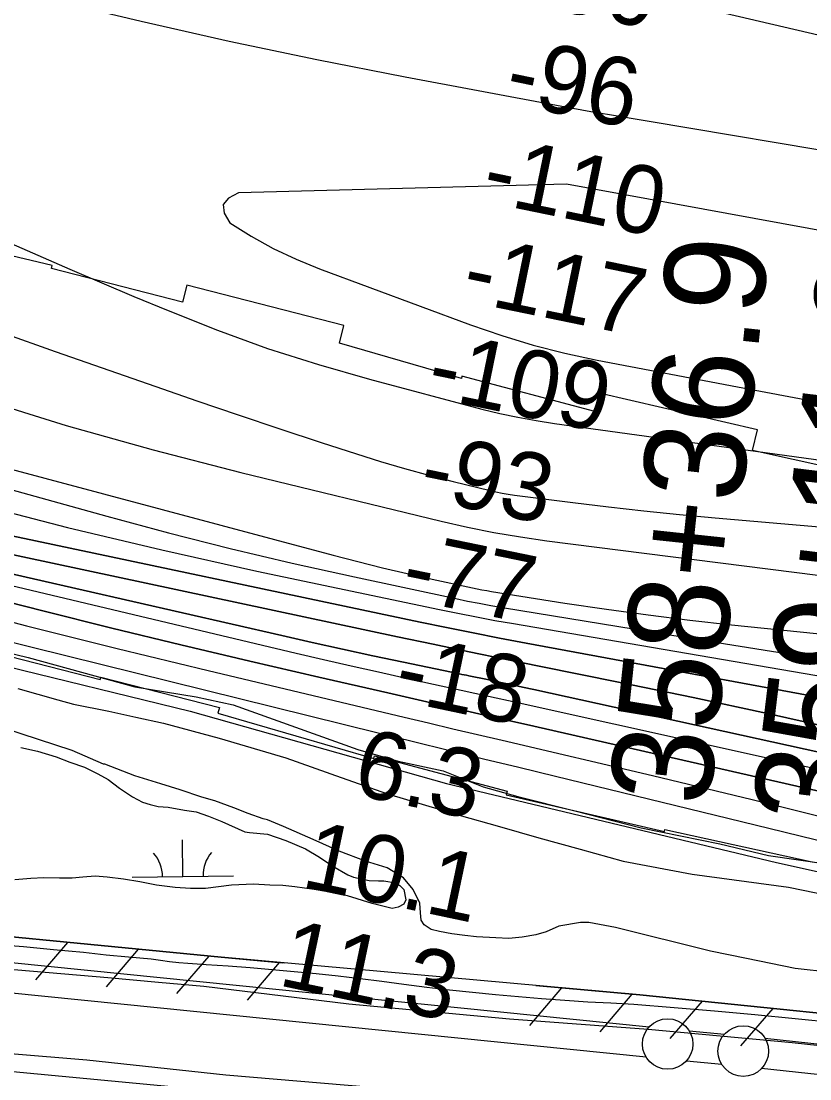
# Model space of a CAD drawing. Extents: x 3704301 to 3742427, y 506229 to 532009.
# Drawn here: x 3712174 to 3712953, y 519013 to 520058 of the extents above; entities that cross this region are included whole.
import ezdxf

# ---------------------------------------------------------------- set-up
doc = ezdxf.new("R2010")
doc.units = 0
for name, color, linetype in [('V-FLOD-BASE', 7, 'Continuous'), ('V-LEVE-TOET', 7, 'Continuous'), ('V-RIVR-EDGE', 7, 'Continuous'), ('V-RIVR-RANG', 7, 'Continuous'), ('V-ROAD-CNTR', 7, 'Continuous'), ('V-RRAP-FSHR', 7, 'Continuous'), ('V-RRAP-RVMT', 7, 'Continuous'), ('V-SITE-VEGE', 7, 'Continuous'), ('V-SURV-IDEN', 7, 'Continuous'), ('V-SURV-LINE', 7, 'Continuous'), ('V-TOPO-DPTH', 7, 'Continuous'), ('V-TOPO-MAJR', 7, 'Continuous'), ('V-TOPO-MINR', 7, 'Continuous'), ('V-TOPO-WATR', 7, 'Continuous'), ('V-WETL-SWMP', 7, 'Continuous')]:
    doc.layers.add(name, color=color, linetype=linetype)

msp = doc.modelspace()

# ---------------------------------------------------------------- linework, layer by layer
at = {"layer": 'V-FLOD-BASE'}
for points in [[(3712309.3, 519108.6), (3712259.2, 519113.2), (3712123.5, 519124.7)], [(3713057.3, 519035.8), (3712935.8, 519048.8), (3712793.5, 519062.2), (3712656.3, 519072.2), (3712497.5, 519087), (3712354.2, 519104.6), (3712309.3, 519108.6)]]:
    msp.add_lwpolyline(points, dxfattribs=at)
at = {"layer": 'V-LEVE-TOET'}
for points in [[(3711586.2, 519172), (3711588.4, 519170.9), (3711722.8, 519116.9), (3711798, 519088.7), (3711821.7, 519081.2), (3711868.5, 519070.4), (3711901.1, 519063.9), (3711971.1, 519056.5), (3712087.4, 519044.5), (3712238.7, 519032.1), (3712375.8, 519017.3), (3712543.6, 519003), (3712718.4, 518986.2), (3712896.6, 518967.7), (3713058.8, 518953.9)], [(3712978.7, 519068.5), (3712938.9, 519072.5), (3712899, 519076.4), (3712859.1, 519080.1), (3712819.2, 519083.5), (3712779.3, 519086.8), (3712756.5, 519087.9), (3712733.7, 519089.1), (3712710.9, 519090.6), (3712688.1, 519092.3), (3712665.4, 519094.2), (3712642.6, 519096.3), (3712619.9, 519098.5), (3712597.2, 519101), (3712574.5, 519103.7), (3712551.9, 519106.6), (3712530.3, 519109.4), (3712508.6, 519112.1), (3712487, 519114.6), (3712465.3, 519117), (3712443.6, 519119.1), (3712421.9, 519121.1), (3712400.1, 519122.9), (3712378.4, 519124.5), (3712356.6, 519126), (3712347.5, 519126.5), (3712338.4, 519127.2), (3712329.4, 519128), (3712320.3, 519129), (3712311.3, 519130.2), (3712302.3, 519131.5), (3712279.9, 519133.4), (3712257.5, 519135.6), (3712235.1, 519138), (3712205.5, 519140.9), (3712175.8, 519143.6), (3712146.1, 519146.1)]]:
    msp.add_lwpolyline(points, dxfattribs=at)
at = {"layer": 'V-RIVR-EDGE'}
msp.add_lwpolyline([(3711522.5, 519662.9), (3711583.7, 519639.3), (3711661.7, 519603.7), (3711684.4, 519586.3), (3711714.3, 519538.2), (3711754.5, 519519.4), (3711864.3, 519485), (3711918.3, 519483.6), (3711999.3, 519464.8), (3712076.1, 519455), (3712180.5, 519429.5), (3712286.1, 519400.5), (3712346.7, 519390.7), (3712383.3, 519382.8), (3712506.3, 519338.7), (3712546.4, 519327.2), (3712590.8, 519317.5), (3712630.4, 519301.8), (3712664.6, 519292.1), (3712721, 519278.1), (3712786.4, 519261.2), (3712864.4, 519245.4), (3712912.4, 519233.8), (3713028.8, 519217.3)], dxfattribs=at)
at = {"layer": 'V-ROAD-CNTR'}
msp.add_lwpolyline([(3713157.6, 518919.9), (3712918.7, 518948.2), (3712531.1, 518985.5), (3712067.6, 519029.6), (3711906, 519048.2), (3711880.7, 519050.4), (3711857.5, 519053.6), (3711843.4, 519056.9), (3711828.4, 519062.3), (3711804.8, 519068.1), (3711783.6, 519074.2), (3711747.7, 519088.7), (3711454.3, 519226.5), (3711379.5, 519260.4), (3711253.9, 519313.1), (3711117.8, 519371.9), (3710938, 519451.5), (3710654.9, 519565.5), (3710319.9, 519704.9), (3710100.2, 519789)], dxfattribs=at)
at = {"layer": 'V-RRAP-FSHR'}
for p, q in [((3712219.6, 519148.1), (3712187.9, 519111)), ((3712289.3, 519141.3), (3712257.6, 519104.2)), ((3712359, 519134.6), (3712327.2, 519097.5)), ((3712428.7, 519128.2), (3712397.2, 519090.9)), ((3712707.6, 519103.3), (3712676.1, 519065.9)), ((3712777.3, 519097), (3712745.8, 519059.7)), ((3712846.9, 519090), (3712815, 519053.1)), ((3712916.6, 519082.9), (3712884.6, 519045.9))]:
    msp.add_line(p, q, dxfattribs=at)
for points in [[(3709741.8, 520362.4), (3710017.7, 520222), (3710534.8, 519997.8), (3710940.4, 519847.9), (3711083.4, 519806), (3711220.5, 519772.7), (3711363.5, 519722.1), (3711531.9, 519623.8), (3711655.2, 519570.7), (3711808.3, 519520), (3711956.1, 519471.1), (3712143.5, 519424.7), (3712340.7, 519376.7), (3712594.2, 519305.2), (3712920.3, 519227.2), (3713163.8, 519173.1), (3713383, 519116.6), (3713629.9, 519034.4)], [(3713107.9, 519063.3), (3712785.1, 519096.3), (3712371.4, 519133.4), (3712005, 519169), (3711979.2, 519171.5), (3711951.5, 519178.8), (3711919.2, 519185.7), (3711888.2, 519193.2), (3711846.9, 519208.1), (3711688.8, 519275.3), (3711690.4, 519291.5), (3711692, 519302.8), (3711691.2, 519314), (3711687.9, 519322), (3711683.4, 519329.2), (3711679.4, 519332.2), (3711670.9, 519339.4), (3711537.2, 519400.4)], [(3713107.9, 519063.3), (3712785.1, 519096.3), (3712371.4, 519133.4), (3712005, 519169), (3711979.2, 519171.5), (3711951.5, 519178.8), (3711919.2, 519185.7), (3711888.2, 519193.2), (3711846.9, 519208.1), (3711688.8, 519275.3), (3711690.4, 519291.5), (3711692, 519302.8), (3711691.2, 519314), (3711687.9, 519322), (3711683.4, 519329.2), (3711679.4, 519332.2), (3711670.9, 519339.4), (3711537.2, 519400.4)], [(3711693, 519273.5), (3711846.9, 519208.1), (3711888.2, 519193.2), (3711919.2, 519185.7), (3711951.5, 519178.8), (3711979.2, 519171.5), (3712005, 519169), (3712371.4, 519133.4), (3712431.7, 519128)], [(3711725.5, 519259.7), (3711846.9, 519208.1), (3711888.2, 519193.2), (3711919.2, 519185.7), (3711951.5, 519178.8), (3711979.2, 519171.5), (3712005, 519169), (3712371.4, 519133.4), (3712433.9, 519127.8)], [(3712682.4, 519105.5), (3712785.1, 519096.3), (3713107.9, 519063.3), (3713318.5, 519044.2), (3713343.3, 519041.8), (3713357.6, 519037.2), (3713370.3, 519031.9), (3713371.6, 519030.7)], [(3712686.6, 519105.1), (3712785.1, 519096.3), (3713107.9, 519063.3), (3713318.5, 519044.2), (3713343.3, 519041.8), (3713357.6, 519037.2), (3713357.9, 519037.1)]]:
    msp.add_lwpolyline(points, dxfattribs=at)
at = {"layer": 'V-RRAP-RVMT'}
for p, q in [((3712204.3, 519816.8), (3712080, 519846.6)), ((3712203.6, 519813.8), (3712204.3, 519816.8)), ((3712333.1, 519780.7), (3712203.6, 519813.8)), ((3712337.3, 519797.4), (3712333.1, 519780.7)), ((3712492.7, 519757.7), (3712337.3, 519797.4)), ((3712488.2, 519740.2), (3712492.7, 519757.7)), ((3712608.8, 519705.2), (3712488.2, 519740.2)), ((3712609.4, 519707.5), (3712608.8, 519705.2)), ((3712740.7, 519672.5), (3712609.4, 519707.5)), ((3712744.9, 519690.9), (3712740.7, 519672.5)), ((3712901.4, 519654.6), (3712744.9, 519690.9)), ((3712896.7, 519634.1), (3712901.4, 519654.6)), ((3713023.2, 519606.2), (3712896.7, 519634.1)), ((3712114.4, 519443), (3712251.8, 519407.9)), ((3712251.8, 519407.9), (3712252.4, 519410.1)), ((3712252.4, 519410.1), (3712369.6, 519380.1)), ((3712369.6, 519380.1), (3712367.9, 519374.6)), ((3712367.9, 519374.6), (3712522.1, 519329.7)), ((3712522.1, 519329.7), (3712522.9, 519332.4)), ((3712522.9, 519332.4), (3712653.9, 519297.5)), ((3712653.9, 519297.5), (3712653.1, 519294)), ((3712653.1, 519294), (3712809.6, 519257.8)), ((3712809.6, 519257.8), (3712810, 519259.6)), ((3712810, 519259.6), (3712955.4, 519227.6))]:
    msp.add_line(p, q, dxfattribs=at)
at = {"layer": 'V-SITE-VEGE'}
for points in [[(3712170.5, 519398.8), (3712209.8, 519387.6), (3712225.3, 519383.4), (3712260.4, 519376.4), (3712287.1, 519370.5), (3712314.5, 519364.6), (3712369.2, 519349.9), (3712435.3, 519330.4), (3712490.1, 519310.9), (3712535.9, 519295), (3712573.4, 519283.8), (3712606.7, 519273.8), (3712646.6, 519262.6), (3712685.2, 519251.3), (3712726.3, 519240.1), (3712768.6, 519228.4), (3712837, 519215.4), (3712932.1, 519202.6), (3713012.5, 519186.1)], [(3712726.5, 519167.6), (3712705.1, 519164), (3712692.6, 519158.6), (3712682.5, 519155.6), (3712668.8, 519153.2), (3712655.8, 519152), (3712642.7, 519152.5), (3712623.6, 519153.7), (3712612.3, 519154.8), (3712599.2, 519156.6), (3712587.3, 519158.9), (3712579, 519160.7), (3712571.9, 519165.4), (3712568.9, 519170.2), (3712568.3, 519177.3), (3712567.7, 519186.8), (3712561.1, 519200.5), (3712551.5, 519211.8), (3712535.5, 519221.8), (3712514, 519228.3), (3712487.9, 519238.4), (3712462.3, 519249.6), (3712433.1, 519262.6), (3712417, 519269.1), (3712412.8, 519270.3), (3712398, 519275.6), (3712383.7, 519281), (3712365.2, 519288), (3712352.1, 519291.6), (3712330.7, 519298.7), (3712311.7, 519304.6), (3712286.1, 519312.8), (3712256.3, 519324.1), (3712255.1, 519324.1), (3712224.2, 519337.7), (3712157.5, 519359.5)], [(3712974.6, 519118.2), (3712938.9, 519122.3), (3712890.7, 519132.3), (3712855, 519139.4), (3712761, 519162.9), (3712734.8, 519167.6), (3712726.5, 519167.6)]]:
    msp.add_lwpolyline(points, dxfattribs=at)
at = {"layer": 'V-SURV-LINE'}
for points in [[(3711902.6, 519154.5), (3712794.3, 519064.7)], [(3712791.3, 519034.8), (3711899.6, 519124.6)], [(3712834, 519060.8), (3712868.9, 519057.5)], [(3712908.9, 519053.4), (3713308.9, 519010)], [(3712866.1, 519027.6), (3712831.2, 519030.9)], [(3713305.6, 518980.2), (3712905.6, 519023.6)]]:
    msp.add_lwpolyline(points, dxfattribs=at)
for centre in [(3712812.7, 519047.7), (3712887.4, 519040.7)]:
    msp.add_circle(centre, 25, dxfattribs=at)
at = {"layer": 'V-TOPO-DPTH'}
for points in [[(3712985, 519357.8), (3712911.5, 519374.3), (3712837.8, 519390.1), (3712764.1, 519405.3), (3712687.3, 519420.7), (3712651.8, 519427.9), (3712616.4, 519435.2), (3712580.9, 519442.6), (3712545.5, 519450.1), (3711863.2, 519595.7), (3711858.3, 519596.8), (3711853.4, 519598), (3711848.6, 519599.3), (3711843.8, 519600.7), (3711839, 519602.3), (3711834.2, 519603.9), (3711829.5, 519605.7), (3711824.9, 519607.6), (3711402.4, 519787.5)], [(3711402.4, 519787.5), (3711824.9, 519607.6), (3711829.5, 519605.7), (3711834.2, 519603.9), (3711839, 519602.3), (3711843.8, 519600.7), (3711848.6, 519599.3), (3711853.4, 519598), (3711858.3, 519596.8), (3711863.2, 519595.7), (3712545.5, 519450.1), (3712580.9, 519442.6), (3712616.4, 519435.2), (3712651.8, 519427.9), (3712687.3, 519420.7), (3712764.1, 519405.3), (3712837.8, 519390.1), (3712911.5, 519374.3), (3712985, 519357.8)], [(3713061.3, 519371.9), (3712672.7, 519443.8), (3712646.5, 519448.8), (3712620.3, 519453.9), (3712594.1, 519459.2), (3712567.9, 519464.6), (3712147.1, 519553.5), (3712095.8, 519565), (3712044.7, 519577.3), (3711993.9, 519590.8), (3711943.3, 519605.2), (3711903.6, 519616.9), (3711873.1, 519626.5), (3711842.9, 519636.5), (3711812.9, 519647.5), (3711783.1, 519658.9), (3711606.5, 519729.9), (3711516.4, 519766.1)], [(3713061.3, 519371.9), (3712672.7, 519443.8), (3712646.5, 519448.8), (3712620.3, 519453.9), (3712594.1, 519459.2), (3712567.9, 519464.6), (3712147.1, 519553.5), (3712095.8, 519565), (3712044.7, 519577.3), (3711993.9, 519590.8), (3711943.3, 519605.2), (3711903.6, 519616.9), (3711873.1, 519626.5), (3711842.9, 519636.5), (3711812.9, 519647.5), (3711783.1, 519658.9), (3711606.5, 519729.9), (3711516.4, 519766.1)], [(3711417, 519686.3), (3711759.7, 519561.6), (3711788.8, 519551.4), (3711817.9, 519541.5), (3711847.3, 519532.2), (3711876.8, 519523.3), (3711927.8, 519508.3), (3711983.1, 519492.5), (3712038.4, 519477.2), (3712093.9, 519462.6), (3712149.6, 519448.5), (3712526.7, 519355.1), (3712561.4, 519346.6), (3712596.1, 519338), (3712630.8, 519329.5), (3712665.6, 519321.1), (3712701.7, 519312.3), (3712754.5, 519299.5), (3712807.2, 519286.7), (3712860, 519273.8), (3712912.8, 519260.9), (3713498.6, 519117.6)], [(3711496.7, 519686.3), (3711578.2, 519655.6), (3711660.3, 519626.2), (3711795.5, 519579.9), (3711810.4, 519575), (3711825.4, 519570.3), (3711840.6, 519566), (3711855.8, 519562), (3712195.2, 519475.7), (3712263.3, 519458.7), (3712331.4, 519442), (3712399.6, 519425.9), (3712467.9, 519410.1), (3712536, 519394.6), (3712570.3, 519386.8), (3712604.7, 519379), (3712639, 519371.1), (3712673.3, 519363.3), (3713027.2, 519282.6)], [(3713027.2, 519282.6), (3712673.3, 519363.3), (3712639, 519371.1), (3712604.7, 519379), (3712570.3, 519386.8), (3712536, 519394.6), (3712467.9, 519410.1), (3712399.6, 519425.9), (3712331.4, 519442), (3712263.3, 519458.7), (3712195.2, 519475.7), (3711855.8, 519562), (3711840.6, 519566), (3711825.4, 519570.3), (3711810.4, 519575), (3711795.5, 519579.9), (3711660.3, 519626.2), (3711578.2, 519655.6), (3711496.7, 519686.3)], [(3713514.9, 519214.4), (3712680.5, 519397.9), (3712669.1, 519400.4), (3712657.6, 519402.8), (3712646.1, 519405.3), (3712634.6, 519407.7), (3712616.2, 519411.5), (3712613.9, 519412), (3712611.6, 519412.5), (3712609.4, 519412.9), (3712607.1, 519413.4), (3712551.5, 519425), (3712521.4, 519431.3), (3712491.3, 519437.8), (3712461.3, 519444.4), (3712431.4, 519451.2), (3711841.9, 519585.8)], [(3711841.9, 519585.8), (3712431.4, 519451.2), (3712461.3, 519444.4), (3712491.3, 519437.8), (3712521.4, 519431.3), (3712551.5, 519425), (3712607.1, 519413.4), (3712609.4, 519412.9), (3712611.6, 519412.5), (3712613.9, 519412), (3712616.2, 519411.5), (3712634.6, 519407.7), (3712646.1, 519405.3), (3712657.6, 519402.8), (3712669.1, 519400.4), (3712680.5, 519397.9), (3713514.9, 519214.4)]]:
    msp.add_lwpolyline(points, dxfattribs=at)
at = {"layer": 'V-TOPO-MAJR'}
for points in [[(3713725.9, 519800.4), (3713628.8, 519819), (3713619.4, 519820.8), (3713609.9, 519822.5), (3713600.5, 519824.2), (3713591, 519825.8), (3713421.2, 519854.2), (3713326.8, 519870), (3713232.4, 519885.8), (3713138, 519901.6), (3713043.6, 519917.4), (3712753.1, 519966.1), (3712740.5, 519968.2), (3712727.9, 519970.4), (3712715.3, 519972.7), (3712702.8, 519975), (3712553.2, 520003.1), (3712466, 520020.2), (3712379.1, 520038.3), (3712292.4, 520057.8), (3712206, 520078.3)], [(3712158.6, 519840.9), (3712190.1, 519827.1), (3712221.7, 519813.4), (3712253.4, 519799.9), (3712285.1, 519786.4), (3712318.8, 519772.3), (3712367.8, 519752.9), (3712417.2, 519735), (3712467.4, 519719.1), (3712518, 519704.5), (3712629, 519675.1), (3712646.8, 519670.8), (3712664.6, 519666.9), (3712682.6, 519663.6), (3712700.7, 519660.8), (3712909.1, 519632.1), (3713018.8, 519616.9)], [(3711497.1, 519796.5), (3711567.3, 519768.7), (3711637.6, 519741.4), (3711708, 519714.4), (3711814.1, 519674.1), (3711831.7, 519667.6), (3711849.3, 519661.5), (3711867.1, 519655.8), (3711885, 519650.4), (3712033.8, 519607.7), (3712126.4, 519582.2), (3712219.3, 519558), (3712312.8, 519535.8), (3712406.5, 519515), (3712587.1, 519477), (3712605.3, 519473.3), (3712623.6, 519469.7), (3712641.9, 519466.3), (3712660.2, 519463.1), (3713384.9, 519339.1)]]:
    msp.add_lwpolyline(points, dxfattribs=at)
at = {"layer": 'V-TOPO-MINR'}
for points in [[(3713768.2, 519867), (3713629.1, 519892.7), (3713624.9, 519893.4), (3713620.7, 519894.2), (3713616.6, 519895), (3713612.4, 519895.8), (3713574.9, 519903.2), (3713551.9, 519907.9), (3713529, 519912.7), (3713506.2, 519917.7), (3713483.4, 519922.9), (3712753.5, 520093.2)], [(3711117.1, 520073.1), (3711647.4, 519863), (3711685.8, 519847.8), (3711724.3, 519832.6), (3711762.7, 519817.4), (3711801.2, 519802.3), (3711857.4, 519780.2), (3711867.8, 519776.2), (3711878.3, 519772.3), (3711888.8, 519768.5), (3711899.3, 519764.8), (3712047.5, 519713.4), (3712132.5, 519685.4), (3712218, 519658.9), (3712304.2, 519634.8), (3712390.9, 519612.4), (3712588.9, 519564.2), (3712614.9, 519558.4), (3712640.9, 519553.1), (3712667.1, 519548.7), (3712693.4, 519544.9), (3713083.4, 519495.3)], [(3711228.8, 519931.9), (3711640.8, 519761.9), (3711676.1, 519747.6), (3711711.5, 519733.7), (3711747.1, 519720.2), (3711782.8, 519707), (3711839.1, 519686.7), (3711846.8, 519684), (3711854.5, 519681.5), (3711862.3, 519679.1), (3711870.1, 519676.9), (3712258.3, 519569.2), (3712319.2, 519552.9), (3712380.2, 519537.4), (3712441.5, 519522.9), (3712503, 519509.2), (3712603.4, 519487.8), (3712614.9, 519485.4), (3712626.4, 519483.2), (3712637.9, 519481.1), (3712649.4, 519479.1), (3712845.2, 519447.1), (3712954.7, 519429.7)], [(3713566.3, 519741.1), (3712712.7, 519897.4), (3712388.4, 519888.6), (3712378.7, 519883.4), (3712373.3, 519877), (3712374.4, 519868.7), (3712379.8, 519859.1), (3712401, 519845.8), (3712422.8, 519833.6), (3712445.4, 519823), (3712468.6, 519813.5), (3712617.9, 519758.3), (3712648.7, 519747.8), (3712679.7, 519738.3), (3712711.2, 519730.4), (3712743, 519723.5), (3712881.8, 519696.9), (3712983.3, 519677.9)], [(3711459.3, 519880.9), (3711531.2, 519848.1), (3711858.6, 519696.9), (3712481.9, 519530.7), (3712506.3, 519524.4), (3712530.8, 519518.3), (3712555.3, 519512.6), (3712579.9, 519507), (3712619.7, 519498.4), (3712624.4, 519497.4), (3712629.1, 519496.5), (3712633.9, 519495.7), (3712638.6, 519494.9), (3712711.2, 519483.4), (3712752.3, 519477.3), (3712793.4, 519471.6), (3712834.6, 519466.6), (3712875.9, 519462), (3713541.7, 519393.9)], [(3711402.4, 519787.5), (3711824.9, 519607.6), (3711829.5, 519605.7), (3711834.2, 519603.9), (3711839, 519602.3), (3711843.8, 519600.7), (3711848.6, 519599.3), (3711853.4, 519598), (3711858.3, 519596.8), (3711863.2, 519595.7), (3712545.5, 519450.1), (3712580.9, 519442.6), (3712616.4, 519435.2), (3712651.8, 519427.9), (3712687.3, 519420.7), (3712764.1, 519405.3), (3712837.8, 519390.1), (3712911.5, 519374.3), (3712985, 519357.8)], [(3711516.4, 519766.1), (3711606.5, 519729.9), (3711783.1, 519658.9), (3711812.9, 519647.5), (3711842.9, 519636.5), (3711873.1, 519626.5), (3711903.6, 519616.9), (3711943.3, 519605.2), (3711993.9, 519590.8), (3712044.7, 519577.3), (3712095.8, 519565), (3712147.1, 519553.5), (3712567.9, 519464.6), (3712594.1, 519459.2), (3712620.3, 519453.9), (3712646.5, 519448.8), (3712672.7, 519443.8), (3713061.3, 519371.9)], [(3712155.4, 519750.3), (3712207.3, 519731.8), (3712306.6, 519697.3), (3712347.4, 519683.2), (3712388.3, 519669.3), (3712429.3, 519655.6), (3712470.3, 519642.1), (3712505, 519630.8), (3712528.8, 519623.4), (3712552.6, 519616.3), (3712576.6, 519609.7), (3712600.7, 519603.5), (3712637.1, 519594.6), (3712643, 519593.3), (3712649, 519592), (3712655.1, 519591), (3712661.2, 519590.1), (3712719, 519582.7), (3712754.1, 519578.4), (3712789.2, 519574.4), (3712824.3, 519570.9), (3712859.5, 519567.6), (3713562.4, 519507)], [(3711471, 519712.7), (3711529.3, 519687.5), (3711588, 519663.5), (3711647.5, 519641.3), (3711707.4, 519620.4), (3711808.8, 519586.9), (3711818.5, 519583.8), (3711828.2, 519580.9), (3711838, 519578.3), (3711847.9, 519575.8), (3712445.5, 519434), (3712472.6, 519427.6), (3712499.8, 519421.4), (3712526.9, 519415.3), (3712554.1, 519409.3), (3712581.3, 519403.3), (3712608.5, 519397.4), (3712635.7, 519391.4), (3712662.9, 519385.4), (3713329.7, 519237.7)], [(3711496.7, 519686.3), (3711578.2, 519655.6), (3711660.3, 519626.2), (3711795.5, 519579.9), (3711810.4, 519575), (3711825.4, 519570.3), (3711840.6, 519566), (3711855.8, 519562), (3712195.2, 519475.7), (3712263.3, 519458.7), (3712331.4, 519442), (3712399.6, 519425.9), (3712467.9, 519410.1), (3712536, 519394.6), (3712570.3, 519386.8), (3712604.7, 519379), (3712639, 519371.1), (3712673.3, 519363.3), (3713027.2, 519282.6)], [(3711486.4, 519675.8), (3711577.8, 519642.7), (3711779.3, 519571.6), (3711800.6, 519564.3), (3711822, 519557.3), (3711843.6, 519550.9), (3711865.3, 519544.7), (3712000.2, 519508), (3712089.5, 519484.1), (3712178.9, 519460.8), (3712268.6, 519438.5), (3712358.4, 519416.7), (3712552.1, 519370.7), (3712576.3, 519365), (3712600.5, 519359.2), (3712624.8, 519353.5), (3712649, 519347.8), (3712797.7, 519312.9), (3712896.2, 519289.2), (3712994.4, 519265)], [(3711841.9, 519585.8), (3712431.4, 519451.2), (3712461.3, 519444.4), (3712491.3, 519437.8), (3712521.4, 519431.3), (3712551.5, 519425), (3712607.1, 519413.4), (3712609.4, 519412.9), (3712611.6, 519412.5), (3712613.9, 519412), (3712616.2, 519411.5), (3712634.6, 519407.7), (3712646.1, 519405.3), (3712657.6, 519402.8), (3712669.1, 519400.4), (3712680.5, 519397.9), (3713514.9, 519214.4)]]:
    msp.add_lwpolyline(points, dxfattribs=at)
at = {"layer": 'V-TOPO-WATR'}
msp.add_lwpolyline([(3711417, 519686.3), (3711759.7, 519561.6), (3711788.8, 519551.4), (3711817.9, 519541.5), (3711847.3, 519532.2), (3711876.8, 519523.3), (3711927.8, 519508.3), (3711983.1, 519492.5), (3712038.4, 519477.2), (3712093.9, 519462.6), (3712149.6, 519448.5), (3712526.7, 519355.1), (3712561.4, 519346.6), (3712596.1, 519338), (3712630.8, 519329.5), (3712665.6, 519321.1), (3712701.7, 519312.3), (3712754.5, 519299.5), (3712807.2, 519286.7), (3712860, 519273.8), (3712912.8, 519260.9), (3713498.6, 519117.6)], dxfattribs=at)
at = {"layer": 'V-WETL-SWMP'}
for p, q in [((3712333.4, 519213.3), (3712333, 519249.3)), ((3712283.4, 519212.7), (3712383.4, 519213.9))]:
    msp.add_line(p, q, dxfattribs=at)
for points in [[(3712173.4, 519340.8), (3712189.9, 519337.1), (3712208.4, 519331.5), (3712221.6, 519326.3), (3712236.3, 519321.1), (3712249.5, 519314.5), (3712259.5, 519308.9), (3712270.8, 519300.4), (3712283.6, 519291.9), (3712293.5, 519286.8), (3712301.1, 519284.4), (3712309.2, 519282.5), (3712319.1, 519281.6), (3712335.2, 519278.8), (3712346.5, 519277), (3712358.8, 519272.7), (3712372.1, 519267.6), (3712394.8, 519257.2), (3712399.5, 519256.8), (3712417, 519254.9), (3712435.4, 519248.8), (3712454.8, 519240.4), (3712468.6, 519232.4), (3712481.8, 519223.4), (3712496.5, 519214.9), (3712502.2, 519212.6), (3712513.1, 519210.2), (3712517.8, 519209.3), (3712526.8, 519208.9), (3712532, 519208.9), (3712543.8, 519207), (3712548, 519204.2), (3712551.8, 519200.4), (3712553.8, 519190), (3712551.9, 519185.8), (3712546.2, 519182.9), (3712540.5, 519181.5), (3712520.7, 519186.6), (3712496.1, 519194.1), (3712476.7, 519197.9), (3712463.4, 519200.2), (3712444.1, 519203), (3712432.2, 519204.4), (3712419.5, 519204.8), (3712403.4, 519205.7), (3712381.7, 519204.7), (3712355.7, 519201.4), (3712341, 519201.3), (3712325.9, 519202.2), (3712307.4, 519204.5), (3712290.9, 519207.8), (3712274.8, 519210.6)], [(3712274.8, 519210.6), (3712258.7, 519212.5), (3712246.9, 519213.4), (3712234.6, 519212.4), (3712224.2, 519211.4), (3712211.5, 519211.4), (3712195.9, 519211.8), (3712183.1, 519211.3), (3712167.5, 519209.9)]]:
    msp.add_lwpolyline(points, dxfattribs=at)
for centre, start, end in [((3712278.2, 519213.1), 359.9282, 41.4719), ((3712388.6, 519214.4), 139.9282, 181.4719)]:
    msp.add_arc(centre, 35.2, start, end, dxfattribs=at)

# ---------------------------------------------------------------- texts
at = {"layer": 'V-RIVR-RANG'}
for s, rotation, p in [('-90', 348.3712, (3712669.2, 520076.3)), ('-96', 348.3712, (3712649.6, 519978.3)), ('-110', 348.3712, (3712626.9, 519880.9)), ('-117', 348.3712, (3712607.2, 519782.8)), ('-109', 348.3712, (3712572.6, 519687.8)), ('-93', 348.3712, (3712564.9, 519587.3)), ('-77', 348.3712, (3712547.1, 519488.9)), ('-18', 348.0883, (3712540, 519388.6)), ('-18', 348.0883, (3712540, 519388.6)), ('6.3', 348.0883, (3712499.7, 519294.9)), ('6.3', 348.0883, (3712499.7, 519294.9)), ('10.1', 348.0883, (3712449.2, 519203.4)), ('10.1', 348.0883, (3712449.2, 519203.4)), ('11.3', 348.0883, (3712426.4, 519106)), ('11.3', 348.0883, (3712426.4, 519106))]:
    msp.add_text(s, height=67, rotation=rotation, dxfattribs=at).set_placement(p)
at = {"layer": 'V-SURV-IDEN'}
for s, rotation, p in [('358+36.9', 83.9308, (3712853.9, 519281.2)), ('359+11.9', 83.1225, (3712995.2, 519260.7))]:
    msp.add_text(s, height=100, rotation=rotation, dxfattribs=at).set_placement(p)

doc.saveas('drawing.dxf')
